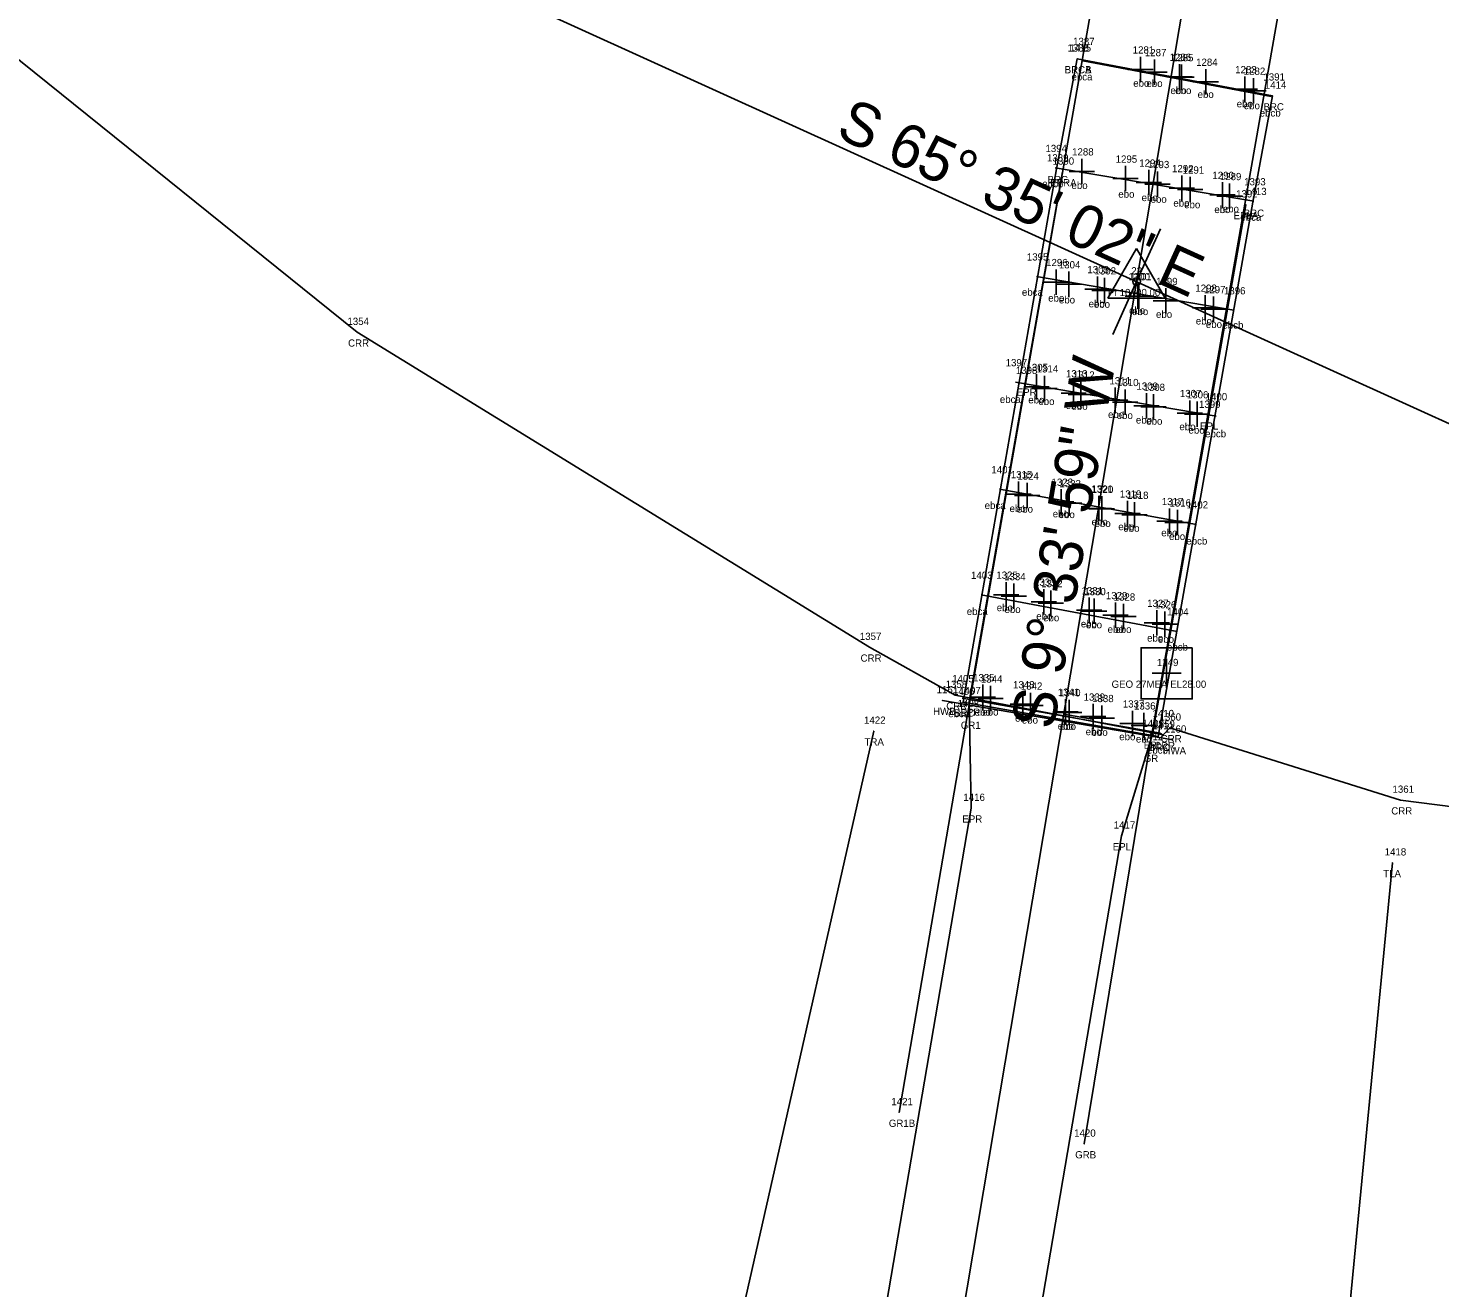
# Model space of a CAD drawing. Extents: x 2432632 to 2433497, y 684847 to 688233.
# Drawn here: x 2432974.5 to 2433169.5, y 685867.7 to 686041.7 of the extents above; entities that cross this region are included whole.
import ezdxf

# ---------------------------------------------------------------- set-up
doc = ezdxf.new("R2010")
doc.units = 0
for name, color, linetype in [('RD_EX_Bridge', 7, 'Continuous'), ('RD_EX_Bridge_txCode', 7, 'Continuous'), ('RD_EX_DV_Prop_txCode', 7, 'Continuous'), ('RD_EX_GuardRail', 7, 'Continuous'), ('RD_EX_GuardRail_txCode', 7, 'Continuous'), ('RD_EX_H2O', 7, 'Continuous'), ('RD_EX_H2O_txCode', 7, 'Continuous'), ('RD_EX_Misc', 7, 'Continuous'), ('RD_EX_Misc_txCode', 7, 'Continuous'), ('RD_EX_Road', 7, 'Continuous'), ('RD_EX_Road_txCode', 7, 'Continuous'), ('RD_EX_VEG', 7, 'Continuous'), ('RD_EX_VEG_txCode', 7, 'Continuous'), ('RD_HC_Cl', 7, 'Continuous'), ('RD_HC_Data', 7, 'Continuous'), ('RD_HC_Data_Tic', 7, 'Continuous'), ('RD_HC_Survey', 7, 'Continuous'), ('RD_HC_txCode', 7, 'Continuous'), ('RD_SMD_Locator', 7, 'Continuous')]:
    doc.layers.add(name, color=color, linetype=linetype)

msp = doc.modelspace()

# ---------------------------------------------------------------- linework, layer by layer
at = {"layer": 'RD_EX_Bridge'}
msp.add_line((2433132.67, 685943.38), (2433100.81, 685948.82), dxfattribs=at)
msp.add_lwpolyline([(2433119.44, 686037.45), (2433116.6, 686022.27), (2433103.68, 685948.59), (2433130.61, 685943.84), (2433143.7, 686017.63), (2433146.43, 686032.32), (2433119.44, 686037.45)], dxfattribs=at)
at = {"layer": 'RD_EX_GuardRail'}
for points in [[(2433136.86, 686137.66), (2433127.75, 686080.87), (2433104.3, 685946.9), (2433094.83, 685891.92)], [(2433162.23, 686133.14), (2433153.01, 686076.72), (2433129.41, 685942.33), (2433120.41, 685887.57)]]:
    msp.add_lwpolyline(points, dxfattribs=at)
at = {"layer": 'RD_EX_H2O'}
msp.add_lwpolyline([(2432923.04, 686077.65), (2433019.93, 685999.69), (2433090.75, 685956.18), (2433102.59, 685949.56), (2433131.31, 685944.06), (2433132.23, 685945.04), (2433164.1, 685935.07), (2433204.66, 685929.9), (2433314.75, 685896.03)], dxfattribs=at)
at = {"layer": 'RD_EX_Misc'}
for p, q in [((2433120.22, 686037.16), (2433146.23, 686032.25)), ((2433128.17, 686037.73), (2433128.17, 686034.23)), ((2433130.14, 686037.36), (2433130.14, 686033.86)), ((2433133.58, 686036.72), (2433133.58, 686033.22)), ((2433133.87, 686036.66), (2433133.87, 686033.16)), ((2433129.92, 686035.98), (2433126.42, 686035.98)), ((2433131.89, 686035.61), (2433128.39, 686035.61)), ((2433135.33, 686034.97), (2433131.83, 686034.97)), ((2433135.62, 686034.91), (2433132.12, 686034.91)), ((2433137.21, 686036.03), (2433137.21, 686032.53)), ((2433142.62, 686035.01), (2433142.62, 686031.51)), ((2433143.8, 686034.79), (2433143.8, 686031.29)), ((2433138.96, 686034.28), (2433135.46, 686034.28)), ((2433144.37, 686033.26), (2433140.87, 686033.26)), ((2433145.55, 686033.04), (2433142.05, 686033.04)), ((2433120.08, 686023.65), (2433120.08, 686020.15)), ((2433143.86, 686017.77), (2433116.4, 686022.37)), ((2433121.83, 686021.9), (2433118.33, 686021.9)), ((2433126.1, 686022.65), (2433126.1, 686019.15)), ((2433129.35, 686022.1), (2433129.35, 686018.6)), ((2433130.54, 686021.9), (2433130.54, 686018.4)), ((2433133.89, 686021.34), (2433133.89, 686017.84)), ((2433135.07, 686021.14), (2433135.07, 686017.64)), ((2433127.85, 686020.9), (2433124.35, 686020.9)), ((2433131.1, 686020.35), (2433127.6, 686020.35)), ((2433132.29, 686020.15), (2433128.79, 686020.15)), ((2433135.64, 686019.59), (2433132.14, 686019.59)), ((2433136.82, 686019.39), (2433133.32, 686019.39)), ((2433139.51, 686020.4), (2433139.51, 686016.9)), ((2433140.5, 686020.24), (2433140.5, 686016.74)), ((2433141.26, 686018.65), (2433137.76, 686018.65)), ((2433142.25, 686018.49), (2433138.75, 686018.49)), ((2433116.51, 686008.36), (2433116.51, 686004.86)), ((2433118.28, 686008.05), (2433118.28, 686004.55)), ((2433113.83, 686007.39), (2433141.09, 686002.71)), ((2433118.26, 686006.61), (2433114.76, 686006.61)), ((2433120.03, 686006.3), (2433116.53, 686006.3)), ((2433123.98, 686005.63), (2433120.48, 686005.63)), ((2433124.96, 686005.46), (2433121.46, 686005.46)), ((2433122.23, 686007.38), (2433122.23, 686003.88)), ((2433123.21, 686007.21), (2433123.21, 686003.71)), ((2433127.84, 686006.41), (2433127.84, 686002.91)), ((2433127.94, 686006.4), (2433127.94, 686002.9)), ((2433131.69, 686005.75), (2433131.69, 686002.25)), ((2433129.59, 686004.66), (2433126.09, 686004.66)), ((2433129.69, 686004.65), (2433126.19, 686004.65)), ((2433133.44, 686004), (2433129.94, 686004)), ((2433137.11, 686004.82), (2433137.11, 686001.32)), ((2433138.29, 686004.62), (2433138.29, 686001.12)), ((2433138.86, 686003.07), (2433135.36, 686003.07)), ((2433140.04, 686002.87), (2433136.54, 686002.87)), ((2433113.82, 685993.87), (2433113.82, 685990.37)), ((2433110.89, 685992.78), (2433138.62, 685988.08)), ((2433115.57, 685992.12), (2433112.07, 685992.12)), ((2433116.65, 685991.93), (2433113.15, 685991.93)), ((2433114.9, 685993.68), (2433114.9, 685990.18)), ((2433118.95, 685993), (2433118.95, 685989.5)), ((2433119.93, 685992.83), (2433119.93, 685989.33)), ((2433124.67, 685992.03), (2433124.67, 685988.53)), ((2433126.05, 685991.79), (2433126.05, 685988.29)), ((2433120.7, 685991.25), (2433117.2, 685991.25)), ((2433121.68, 685991.08), (2433118.18, 685991.08)), ((2433126.42, 685990.28), (2433122.92, 685990.28)), ((2433127.8, 685990.04), (2433124.3, 685990.04)), ((2433129, 685991.29), (2433129, 685987.79)), ((2433129.99, 685991.12), (2433129.99, 685987.62)), ((2433135.02, 685990.27), (2433135.02, 685986.77)), ((2433136, 685990.1), (2433136, 685986.6)), ((2433130.75, 685989.54), (2433127.25, 685989.54)), ((2433131.74, 685989.37), (2433128.24, 685989.37)), ((2433136.77, 685988.52), (2433133.27, 685988.52)), ((2433137.75, 685988.35), (2433134.25, 685988.35)), ((2433111.33, 685979.07), (2433111.33, 685975.57)), ((2433112.51, 685978.86), (2433112.51, 685975.36)), ((2433108.68, 685978), (2433135.94, 685973.14)), ((2433113.08, 685977.32), (2433109.58, 685977.32)), ((2433114.26, 685977.11), (2433110.76, 685977.11)), ((2433118.98, 685976.27), (2433115.48, 685976.27)), ((2433117.23, 685978.02), (2433117.23, 685974.52)), ((2433118.32, 685977.83), (2433118.32, 685974.33)), ((2433122.45, 685977.09), (2433122.45, 685973.59)), ((2433122.84, 685977.02), (2433122.84, 685973.52)), ((2433126.39, 685976.39), (2433126.39, 685972.89)), ((2433127.37, 685976.21), (2433127.37, 685972.71)), ((2433120.07, 685976.08), (2433116.57, 685976.08)), ((2433124.2, 685975.34), (2433120.7, 685975.34)), ((2433124.59, 685975.27), (2433121.09, 685975.27)), ((2433128.14, 685974.64), (2433124.64, 685974.64)), ((2433129.12, 685974.46), (2433125.62, 685974.46)), ((2433132.2, 685975.35), (2433132.2, 685971.85)), ((2433133.28, 685975.16), (2433133.28, 685971.66)), ((2433133.95, 685973.6), (2433130.45, 685973.6)), ((2433135.03, 685973.41), (2433131.53, 685973.41)), ((2433109.6, 685965.18), (2433109.6, 685961.68)), ((2433110.68, 685964.98), (2433110.68, 685961.48)), ((2433106.16, 685963.41), (2433133.24, 685958.36)), ((2433111.35, 685963.43), (2433107.85, 685963.43)), ((2433112.43, 685963.23), (2433108.93, 685963.23)), ((2433114.81, 685964.21), (2433114.81, 685960.71)), ((2433115.8, 685964.02), (2433115.8, 685960.52)), ((2433121.11, 685963.03), (2433121.11, 685959.53)), ((2433121.79, 685962.91), (2433121.79, 685959.41)), ((2433116.56, 685962.46), (2433113.06, 685962.46)), ((2433117.55, 685962.27), (2433114.05, 685962.27)), ((2433122.86, 685961.28), (2433119.36, 685961.28)), ((2433123.54, 685961.16), (2433120.04, 685961.16)), ((2433126.49, 685960.61), (2433122.99, 685960.61)), ((2433124.74, 685962.36), (2433124.74, 685958.86)), ((2433125.82, 685962.16), (2433125.82, 685958.66)), ((2433130.44, 685961.29), (2433130.44, 685957.79)), ((2433131.53, 685961.09), (2433131.53, 685957.59)), ((2433127.57, 685960.41), (2433124.07, 685960.41)), ((2433132.19, 685959.54), (2433128.69, 685959.54)), ((2433133.28, 685959.34), (2433129.78, 685959.34)), ((2433106.4, 685951.02), (2433106.4, 685947.52)), ((2433107.48, 685950.83), (2433107.48, 685947.33)), ((2433103.56, 685949.13), (2433130.94, 685944.32)), ((2433108.15, 685949.27), (2433104.65, 685949.27)), ((2433109.23, 685949.08), (2433105.73, 685949.08)), ((2433111.91, 685950.05), (2433111.91, 685946.55)), ((2433113, 685949.86), (2433113, 685946.36)), ((2433117.82, 685949.02), (2433117.82, 685945.52)), ((2433118.32, 685948.93), (2433118.32, 685945.43)), ((2433113.66, 685948.3), (2433110.16, 685948.3)), ((2433114.75, 685948.11), (2433111.25, 685948.11)), ((2433119.57, 685947.27), (2433116.07, 685947.27)), ((2433120.07, 685947.18), (2433116.57, 685947.18)), ((2433121.66, 685948.34), (2433121.66, 685944.84)), ((2433122.85, 685948.14), (2433122.85, 685944.64)), ((2433127.08, 685947.39), (2433127.08, 685943.89)), ((2433128.66, 685947.12), (2433128.66, 685943.62)), ((2433123.41, 685946.59), (2433119.91, 685946.59)), ((2433124.6, 685946.39), (2433121.1, 685946.39)), ((2433128.83, 685945.64), (2433125.33, 685945.64)), ((2433130.41, 685945.37), (2433126.91, 685945.37))]:
    msp.add_line(p, q, dxfattribs=at)
at = {"layer": 'RD_EX_Road'}
for points in [[(2433117.43, 686021.83), (2433112.31, 685992.92), (2433104.52, 685948.7), (2433104.8, 685933.95), (2433088.22, 685836.98), (2433079.44, 685788.63), (2433069.66, 685742.53), (2433057.55, 685694.23)], [(2433142.75, 686017.3), (2433137.62, 685988.23), (2433129.83, 685944.15), (2433125.56, 685930.12), (2433108.96, 685832.94), (2433099.86, 685784.62), (2433089.82, 685738.23), (2433077.66, 685687.92)]]:
    msp.add_lwpolyline(points, dxfattribs=at)
at = {"layer": 'RD_EX_VEG'}
msp.add_line((2433162.99, 685926.41), (2433137.8, 685665.13), dxfattribs=at)
msp.add_lwpolyline([(2433091.33, 685944.6), (2433043.36, 685732.71), (2433025.22, 685647.63)], dxfattribs=at)
at = {"layer": 'RD_HC_Cl'}
for p, q in [((2433147.9, 686126.86), (2433095.19, 685814.15)), ((2433035.76, 686048.38), (2433184.8, 685980.72))]:
    msp.add_line(p, q, dxfattribs=at)
at = {"layer": 'RD_HC_Data'}
for p, q in [((2433123.67, 686004.38), (2433127.64, 686011.26)), ((2433127.64, 686011.26), (2433131.61, 686004.38)), ((2433123.67, 686004.38), (2433131.61, 686004.38))]:
    msp.add_line(p, q, dxfattribs=at)
msp.add_circle((2433127.64, 686006.67), 0.529, dxfattribs=at)
at = {"layer": 'RD_HC_Data_Tic'}
for p, q in [((2433127.64, 686006.67), (2433130.95, 686013.96)), ((2433127.64, 686006.67), (2433124.34, 685999.39)), ((2433117.57, 685946.92), (2433121.52, 685946.25))]:
    msp.add_line(p, q, dxfattribs=at)
at = {"layer": 'RD_HC_Survey'}
for p, q in [((2433131.8, 685950.57), (2433131.8, 685954.57)), ((2433133.8, 685952.57), (2433129.8, 685952.57))]:
    msp.add_line(p, q, dxfattribs=at)
msp.add_lwpolyline([(2433135.33, 685956.1), (2433128.26, 685956.1), (2433128.26, 685949.03), (2433135.33, 685949.03)], close=True, dxfattribs=at)
at = {"layer": 'RD_SMD_Locator'}
for centre in [(2433119.44, 686037.45), (2433119.44, 686037.45), (2433146.43, 686032.32), (2433116.6, 686022.27), (2433117.43, 686021.83), (2433142.75, 686017.3), (2433143.7, 686017.63), (2433127.64, 686006.67), (2433019.93, 685999.69), (2433112.31, 685992.92), (2433137.62, 685988.23), (2433090.75, 685956.18), (2433102.59, 685949.56), (2433100.81, 685948.82), (2433103.68, 685948.59), (2433104.52, 685948.7), (2433104.3, 685946.9), (2433132.23, 685945.04), (2433091.33, 685944.6), (2433129.83, 685944.15), (2433130.61, 685943.84), (2433131.31, 685944.06), (2433132.67, 685943.38), (2433129.41, 685942.33), (2433104.8, 685933.95), (2433164.1, 685935.07), (2433125.56, 685930.12), (2433162.99, 685926.41), (2433094.83, 685891.92), (2433120.41, 685887.57)]:
    msp.add_circle(centre, 0.001, dxfattribs=at)

# ---------------------------------------------------------------- texts
at = {"layer": 'RD_EX_Bridge_txCode'}
for s, p in [('1388', (2433118.09, 686038.45)), ('1415', (2433118.38, 686038.45)), ('BRCA', (2433117.7, 686035.45)), ('BRCB', (2433117.71, 686035.45)), ('1414', (2433145.37, 686033.32)), ('BRC', (2433145.18, 686030.32)), ('1389', (2433115.26, 686023.27)), ('BRC', (2433115.35, 686020.27)), ('1413', (2433142.64, 686018.63)), ('BRC', (2433142.45, 686015.63)), ('1161', (2433100.01, 685949.82)), ('1406', (2433102.27, 685949.59)), ('HWB', (2433099.52, 685946.82)), ('BRC', (2433102.43, 685946.59)), ('1411', (2433129.83, 685944.84)), ('1160', (2433131.54, 685944.38)), ('BRC', (2433129.36, 685941.84)), ('HWA', (2433131.36, 685941.38))]:
    msp.add_text(s, height=1, dxfattribs=at).set_placement(p)
at = {"layer": 'RD_EX_DV_Prop_txCode'}
for s, p in [('1249', (2433130.45, 685953.57)), ('GEO 27MEA EL28.00', (2433124.19, 685950.57))]:
    msp.add_text(s, height=1, dxfattribs=at).set_placement(p)
at = {"layer": 'RD_EX_GuardRail_txCode'}
for s, p in [('1408', (2433102.91, 685947.9)), ('GR1', (2433103.35, 685944.9)), ('1412', (2433128.35, 685943.33)), ('GR', (2433128.63, 685940.33)), ('1421', (2433093.76, 685892.92)), ('GR1B', (2433093.41, 685889.92)), ('1420', (2433119.02, 685888.57)), ('GRB', (2433119.16, 685885.57))]:
    msp.add_text(s, height=1, dxfattribs=at).set_placement(p)
at = {"layer": 'RD_EX_H2O_txCode'}
for s, p in [('1354', (2433018.59, 686000.69)), ('CRR', (2433018.68, 685997.69)), ('1357', (2433089.4, 685957.18)), ('CRR', (2433089.5, 685954.18)), ('1358', (2433101.25, 685950.56)), ('CRR', (2433101.34, 685947.56)), ('1360', (2433130.82, 685946.04)), ('1359', (2433129.97, 685945.06)), ('CRR', (2433130.06, 685942.06)), ('CRR', (2433130.98, 685943.04)), ('1361', (2433163.01, 685936.07)), ('CRR', (2433162.84, 685933.07))]:
    msp.add_text(s, height=1, dxfattribs=at).set_placement(p)
at = {"layer": 'RD_EX_Misc_txCode'}
for s, p in [('1387', (2433118.87, 686039.36)), ('1281', (2433127.11, 686038.18)), ('1287', (2433128.79, 686037.81)), ('1286', (2433132.21, 686037.17)), ('1285', (2433132.53, 686037.11)), ('1284', (2433135.87, 686036.48)), ('ebca', (2433118.65, 686034.47)), ('1283', (2433141.27, 686035.46)), ('1282', (2433142.45, 686035.24)), ('1391', (2433145.17, 686034.45)), ('ebo ', (2433127.18, 686033.59)), ('ebo ', (2433129.01, 686033.56)), ('ebo ', (2433132.32, 686032.58)), ('ebo ', (2433132.99, 686032.58)), ('ebo ', (2433136.08, 686032.04)), ('ebo ', (2433141.48, 686030.74)), ('ebo ', (2433142.46, 686030.49)), ('ebcb', (2433144.66, 686029.48)), ('1394', (2433115.05, 686024.57)), ('1288', (2433118.73, 686024.1)), ('1295', (2433124.75, 686023.1)), ('1294', (2433128.01, 686022.55)), ('1293', (2433129.19, 686022.35)), ('1292', (2433132.54, 686021.79)), ('1291', (2433134.01, 686021.59)), ('1290', (2433138.12, 686020.85)), ('1289', (2433139.15, 686020.69)), ('ebcb', (2433114.61, 686019.7)), ('ebo ', (2433118.65, 686019.46)), ('ebo ', (2433125.12, 686018.26)), ('1393', (2433142.51, 686019.97)), ('ebo ', (2433128.34, 686017.79)), ('ebo ', (2433129.58, 686017.56)), ('ebo ', (2433132.73, 686017.03)), ('ebo ', (2433134.22, 686016.81)), ('ebo ', (2433138.39, 686016.14)), ('ebo ', (2433139.56, 686016.24)), ('ebca', (2433141.98, 686015.08)), ('1395', (2433112.48, 686009.59)), ('1296', (2433115.14, 686008.81)), ('1304', (2433116.9, 686008.5)), ('1303', (2433120.84, 686007.83)), ('1302', (2433121.83, 686007.66)), ('1300', (2433126.52, 686006.85)), ('1301', (2433126.74, 686006.86)), ('ebca', (2433111.8, 686004.72)), ('1299', (2433130.34, 686006.2)), ('1298', (2433135.76, 686005.27)), ('1297', (2433136.95, 686005.07)), ('1396', (2433139.72, 686004.91)), ('ebo ', (2433115.43, 686003.91)), ('ebo ', (2433116.91, 686003.66)), ('ebo ', (2433121.02, 686003.12)), ('ebo ', (2433121.74, 686003.06)), ('ebo ', (2433126.61, 686002.2)), ('ebo ', (2433127.02, 686002.05)), ('ebo ', (2433130.33, 686001.67)), ('ebo ', (2433135.83, 686000.75)), ('ebo ', (2433137.22, 686000.28)), ('ebcb', (2433139.51, 686000.18)), ('1397', (2433109.55, 685994.98)), ('1305', (2433112.43, 685994.32)), ('1314', (2433113.84, 685994.13)), ('1313', (2433117.88, 685993.45)), ('1312', (2433118.87, 685993.28)), ('1311', (2433123.89, 685992.48)), ('1310', (2433124.94, 685992.24)), ('1309', (2433127.62, 685991.74)), ('1308', (2433128.6, 685991.57)), ('ebca', (2433108.75, 685989.91)), ('ebo ', (2433112.68, 685989.85)), ('ebo ', (2433114.07, 685989.63)), ('ebo ', (2433117.86, 685989.09)), ('ebo ', (2433118.65, 685988.96)), ('1307', (2433133.63, 685990.72)), ('1306', (2433134.59, 685990.55)), ('1400', (2433137.19, 685990.28)), ('ebo ', (2433123.7, 685987.83)), ('ebo ', (2433124.9, 685987.7)), ('ebo ', (2433127.55, 685987.07)), ('ebo ', (2433128.98, 685986.91)), ('ebo ', (2433133.56, 685986.15)), ('ebo ', (2433134.82, 685985.68)), ('ebcb', (2433137.12, 685985.17)), ('1401', (2433107.58, 685980.2)), ('1315', (2433110.26, 685979.52)), ('1324', (2433111.16, 685979.31)), ('1323', (2433115.89, 685978.47)), ('1322', (2433116.97, 685978.28)), ('1321', (2433121.39, 685977.54)), ('1320', (2433121.46, 685977.47)), ('ebca', (2433106.65, 685975.26)), ('1319', (2433125.33, 685976.84)), ('1318', (2433126.31, 685976.66)), ('1317', (2433131.13, 685975.8)), ('1316', (2433132.19, 685975.61)), ('1402', (2433134.55, 685975.34)), ('ebo ', (2433110.09, 685974.84)), ('ebo ', (2433111.1, 685974.77)), ('ebo ', (2433116.06, 685974.11)), ('ebo ', (2433116.88, 685974.01)), ('ebo ', (2433121.43, 685973)), ('ebo ', (2433121.84, 685972.78)), ('ebo ', (2433125.12, 685972.34)), ('ebo ', (2433125.82, 685972.12)), ('ebo ', (2433131.06, 685971.49)), ('ebo ', (2433132.13, 685970.98)), ('ebcb', (2433134.52, 685970.36)), ('1403', (2433104.77, 685965.61)), ('1325', (2433108.26, 685965.63)), ('1334', (2433109.34, 685965.43)), ('1333', (2433113.47, 685964.66)), ('1332', (2433114.45, 685964.47)), ('1331', (2433120.04, 685963.48)), ('1330', (2433120.41, 685963.36)), ('1329', (2433123.4, 685962.81)), ('1328', (2433124.48, 685962.61)), ('1327', (2433129.1, 685961.74)), ('1326', (2433130.16, 685961.54)), ('ebca', (2433104.18, 685960.62)), ('ebo ', (2433108.32, 685961.15)), ('ebo ', (2433109.39, 685960.9)), ('ebo ', (2433113.78, 685959.98)), ('ebo ', (2433114.73, 685959.76)), ('1404', (2433131.86, 685960.56)), ('ebo ', (2433119.94, 685958.91)), ('ebo ', (2433120.64, 685958.78)), ('ebo ', (2433123.64, 685958.15)), ('ebo ', (2433124.71, 685958.15)), ('ebo ', (2433129.1, 685956.95)), ('ebo ', (2433130.59, 685956.79)), ('ebcb', (2433131.84, 685955.71)), ('1405', (2433102.17, 685951.33)), ('1335', (2433105.05, 685951.47)), ('1344', (2433106.13, 685951.28)), ('1343', (2433110.57, 685950.5)), ('1342', (2433111.65, 685950.31)), ('1341', (2433116.76, 685949.47)), ('1340', (2433116.93, 685949.38)), ('1339', (2433120.32, 685948.79)), ('1338', (2433121.5, 685948.59)), ('ebca', (2433101.62, 685946.51)), ('ebo ', (2433105.26, 685946.71)), ('ebo ', (2433106.33, 685946.74)), ('ebo ', (2433110.85, 685945.89)), ('1337', (2433125.74, 685947.84)), ('1336', (2433127.29, 685947.57)), ('1410', (2433129.84, 685946.52)), ('ebo ', (2433111.79, 685945.63)), ('ebo ', (2433116.75, 685944.78)), ('ebo ', (2433117.04, 685944.75)), ('ebo ', (2433120.61, 685944.02)), ('ebo ', (2433121.43, 685943.93)), ('ebo ', (2433125.25, 685943.33)), ('ebo ', (2433127.55, 685943.01)), ('ebcb', (2433129.08, 685941.48))]:
    msp.add_text(s, height=1, dxfattribs=at).set_placement(p)
at = {"layer": 'RD_EX_Road_txCode'}
for s, p in [('1390', (2433116.04, 686022.83)), ('EPRA', (2433115.71, 686019.83)), ('1392', (2433141.4, 686018.3)), ('EPLA', (2433141.05, 686015.3)), ('1398', (2433110.96, 685993.92)), ('EPR', (2433111.08, 685990.92)), ('1399', (2433136.27, 685989.23)), ('EPL', (2433136.41, 685986.23)), ('1407', (2433103.14, 685949.7)), ('EPR', (2433103.3, 685946.7)), ('1409', (2433128.45, 685945.15)), ('EPL', (2433128.63, 685942.15)), ('1416', (2433103.71, 685934.95)), ('EPR', (2433103.57, 685931.95)), ('1417', (2433124.49, 685931.12)), ('EPL', (2433124.35, 685928.12))]:
    msp.add_text(s, height=1, dxfattribs=at).set_placement(p)
at = {"layer": 'RD_EX_VEG_txCode'}
for s, p in [('1422', (2433089.98, 685945.6)), ('TRA', (2433090.05, 685942.6)), ('1418', (2433161.93, 685927.41)), ('TLA', (2433161.73, 685924.41))]:
    msp.add_text(s, height=1, dxfattribs=at).set_placement(p)
at = {"layer": 'RD_HC_Data'}
for s, rotation, p in [('S 65%%d 35\' 02" E', 335.584, (2433085.89, 686026.73)), ('S 9%%d 33\' 59" W', 80.4335, (2433116.18, 685944.66))]:
    msp.add_text(s, height=6, rotation=rotation, dxfattribs=at).set_placement(p)
at = {"layer": 'RD_HC_txCode'}
for s, p in [('22', (2433126.91, 686007.67)), ('PI 10+00.00', (2433123.67, 686004.67))]:
    msp.add_text(s, height=1, dxfattribs=at).set_placement(p)

doc.saveas('drawing.dxf')
